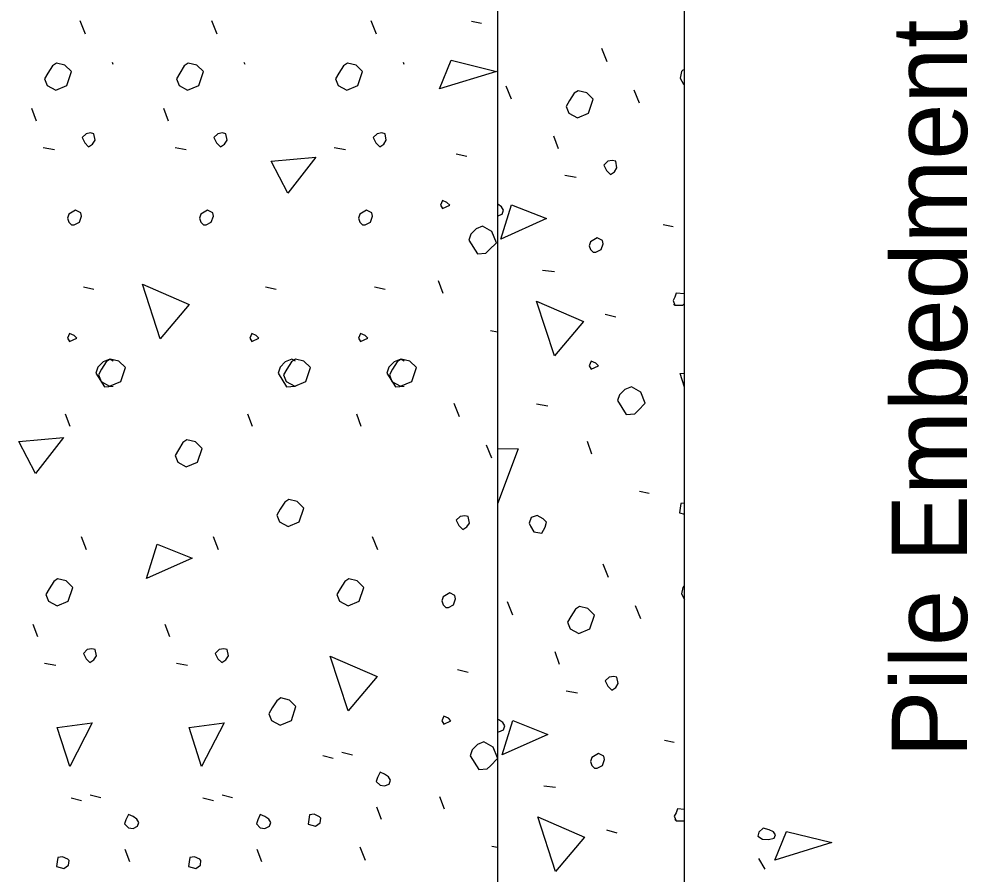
# Model space of a CAD drawing. Extents: x 112310.1 to 112345.4, y 111943.5 to 111959.3.
# Drawn here: x 112320.249 to 112321.522, y 111950.107 to 111951.253 of the extents above; entities that cross this region are included whole.
import ezdxf

# ---------------------------------------------------------------- set-up
doc = ezdxf.new("R2010")
doc.units = 0
for name, color, linetype in [('Miscellaneous', 7, 'Continuous'), ('PileConc', 7, 'Continuous'), ('TextStructures', 7, 'Continuous')]:
    doc.layers.add(name, color=color, linetype=linetype)

msp = doc.modelspace()

# ---------------------------------------------------------------- linework, layer by layer
at = {"layer": 'Miscellaneous'}
for p, q in [((112320.338, 111951.233), (112320.3309, 111951.2506)), ((112320.5149, 111951.233), (112320.5078, 111951.2506)), ((112320.7283, 111951.233), (112320.7212, 111951.2506)), ((112320.8559, 111951.2503), (112320.8691, 111951.2477)), ((112321.0376, 111951.196), (112321.0305, 111951.2137)), ((112320.3753, 111951.1922), (112320.3742, 111951.195)), ((112320.5522, 111951.1922), (112320.5511, 111951.195)), ((112320.7656, 111951.1922), (112320.7645, 111951.195)), ((112320.9094, 111951.1456), (112320.9023, 111951.1633)), ((112321.0809, 111951.1403), (112321.0738, 111951.158)), ((112320.2726, 111951.1163), (112320.2664, 111951.1331)), ((112320.4495, 111951.1163), (112320.4433, 111951.1331)), ((112320.9722, 111951.0793), (112320.966, 111951.0961)), ((112320.2814, 111951.0809), (112320.2964, 111951.0783)), ((112320.4583, 111951.0809), (112320.4733, 111951.0783)), ((112320.6717, 111951.0809), (112320.6867, 111951.0783)), ((112320.8353, 111951.0727), (112320.8494, 111951.0692)), ((112320.981, 111951.044), (112320.996, 111951.0413)), ((112321.1127, 111950.9777), (112321.126, 111950.975)), ((112320.951, 111950.9167), (112320.9669, 111950.9149)), ((112320.3353, 111950.8944), (112320.3495, 111950.8909)), ((112320.5796, 111950.8944), (112320.5937, 111950.8909)), ((112320.7256, 111950.8944), (112320.7398, 111950.8909)), ((112320.8176, 111950.8853), (112320.8114, 111950.9021)), ((112321.0349, 111950.8575), (112321.0491, 111950.8539)), ((112320.8813, 111950.8358), (112320.8907, 111950.834)), ((112320.8397, 111950.72), (112320.8327, 111950.7377)), ((112320.943, 111950.7373), (112320.958, 111950.7346)), ((112320.3176, 111950.707), (112320.3115, 111950.7238)), ((112320.5619, 111950.707), (112320.5557, 111950.7238)), ((112320.708, 111950.707), (112320.7018, 111950.7238)), ((112320.883, 111950.6644), (112320.876, 111950.682)), ((112321.0172, 111950.6701), (112321.0111, 111950.6869)), ((112321.0809, 111950.6206), (112321.0941, 111950.6179)), ((112320.3397, 111950.5418), (112320.3327, 111950.5594)), ((112320.5166, 111950.5418), (112320.5096, 111950.5594)), ((112320.73, 111950.5418), (112320.723, 111950.5594)), ((112321.0393, 111950.5048), (112321.0323, 111950.5225)), ((112320.9112, 111950.4544), (112320.9041, 111950.4721)), ((112321.0827, 111950.4491), (112321.0756, 111950.4668)), ((112320.2743, 111950.4251), (112320.2681, 111950.4419)), ((112320.4512, 111950.4251), (112320.445, 111950.4419)), ((112320.9739, 111950.3881), (112320.9678, 111950.4049)), ((112320.2832, 111950.3897), (112320.2982, 111950.3871)), ((112320.4601, 111950.3897), (112320.4751, 111950.3871)), ((112320.8371, 111950.3815), (112320.8512, 111950.378)), ((112320.9828, 111950.3528), (112320.9978, 111950.3501)), ((112321.1145, 111950.2865), (112321.1277, 111950.2838)), ((112320.6562, 111950.266), (112320.6704, 111950.2624)), ((112320.6819, 111950.2704), (112320.696, 111950.2668)), ((112320.9527, 111950.2255), (112320.9686, 111950.2237)), ((112320.3188, 111950.2092), (112320.333, 111950.2056)), ((112320.3444, 111950.2136), (112320.3586, 111950.21)), ((112320.4957, 111950.2092), (112320.5098, 111950.2056)), ((112320.5213, 111950.2136), (112320.5355, 111950.21)), ((112320.8194, 111950.1941), (112320.8132, 111950.2109)), ((112320.7349, 111950.1802), (112320.7287, 111950.197)), ((112321.0367, 111950.1663), (112321.0508, 111950.1627)), ((112320.883, 111950.1446), (112320.8907, 111950.1431)), ((112320.3975, 111950.1234), (112320.3913, 111950.1402)), ((112320.5744, 111950.1234), (112320.5682, 111950.1402)), ((112320.7137, 111950.1254), (112320.7066, 111950.1431)), ((112321.2495, 111950.1136), (112321.2412, 111950.1281))]:
    msp.add_line(p, q, dxfattribs=at)
for points in [[(112320.2867, 111951.164), (112320.2982, 111951.1578), (112320.3132, 111951.164), (112320.3194, 111951.1826), (112320.3106, 111951.1914), (112320.2991, 111951.1941), (112320.2938, 111951.1905), (112320.2876, 111951.1808), (112320.2832, 111951.1729), (112320.2867, 111951.164)], [(112320.4636, 111951.164), (112320.4751, 111951.1578), (112320.4901, 111951.164), (112320.4963, 111951.1826), (112320.4875, 111951.1914), (112320.476, 111951.1941), (112320.4707, 111951.1905), (112320.4645, 111951.1808), (112320.4601, 111951.1729), (112320.4636, 111951.164)], [(112320.677, 111951.164), (112320.6885, 111951.1578), (112320.7035, 111951.164), (112320.7097, 111951.1826), (112320.7009, 111951.1914), (112320.6894, 111951.1941), (112320.6841, 111951.1905), (112320.6779, 111951.1808), (112320.6735, 111951.1729), (112320.677, 111951.164)], [(112320.8129, 111951.1594), (112320.8286, 111951.1978), (112320.8895, 111951.183), (112320.8129, 111951.1594)], [(112321.1415, 111951.1853), (112321.1392, 111951.1845), (112321.1375, 111951.1827), (112321.1357, 111951.1739)], [(112321.1357, 111951.1739), (112321.1401, 111951.1659), (112321.1415, 111951.1661)], [(112320.9863, 111951.127), (112320.9978, 111951.1209), (112321.0128, 111951.127), (112321.019, 111951.1456), (112321.0102, 111951.1544), (112320.9987, 111951.1571), (112320.9934, 111951.1536), (112320.9872, 111951.1438), (112320.9828, 111951.1359), (112320.9863, 111951.127)], [(112320.3371, 111951.0871), (112320.3424, 111951.0818), (112320.3477, 111951.0853), (112320.3512, 111951.0907), (112320.3495, 111951.0995), (112320.345, 111951.1004), (112320.3389, 111951.0995), (112320.3336, 111951.0942), (112320.3371, 111951.0871)], [(112320.514, 111951.0871), (112320.5193, 111951.0818), (112320.5246, 111951.0853), (112320.5281, 111951.0907), (112320.5263, 111951.0995), (112320.5219, 111951.1004), (112320.5157, 111951.0995), (112320.5104, 111951.0942), (112320.514, 111951.0871)], [(112320.7274, 111951.0871), (112320.7327, 111951.0818), (112320.738, 111951.0853), (112320.7415, 111951.0907), (112320.7398, 111951.0995), (112320.7354, 111951.1004), (112320.7292, 111951.0995), (112320.7239, 111951.0942), (112320.7274, 111951.0871)], [(112320.6094, 111951.0199), (112320.5872, 111951.0628), (112320.6471, 111951.068), (112320.6094, 111951.0199)], [(112321.0367, 111951.0501), (112321.042, 111951.0448), (112321.0473, 111951.0484), (112321.0508, 111951.0537), (112321.0491, 111951.0625), (112321.0446, 111951.0634), (112321.0385, 111951.0625), (112321.0332, 111951.0572), (112321.0367, 111951.0501)], [(112320.8167, 111950.9994), (112320.8265, 111951.0038), (112320.8229, 111951.0073), (112320.8167, 111951.01), (112320.8141, 111951.0038), (112320.8167, 111950.9994)], [(112320.3194, 111950.9775), (112320.3229, 111950.9775), (112320.33, 111950.9811), (112320.3327, 111950.989), (112320.3318, 111950.9934), (112320.3247, 111950.997), (112320.3159, 111950.9917), (112320.3141, 111950.9864), (112320.3159, 111950.9811), (112320.3194, 111950.9775)], [(112320.4963, 111950.9775), (112320.4998, 111950.9775), (112320.5069, 111950.9811), (112320.5096, 111950.989), (112320.5087, 111950.9934), (112320.5016, 111950.997), (112320.4928, 111950.9917), (112320.491, 111950.9864), (112320.4928, 111950.9811), (112320.4963, 111950.9775)], [(112320.7097, 111950.9775), (112320.7133, 111950.9775), (112320.7203, 111950.9811), (112320.723, 111950.989), (112320.7221, 111950.9934), (112320.715, 111950.997), (112320.7062, 111950.9917), (112320.7044, 111950.9864), (112320.7062, 111950.9811), (112320.7097, 111950.9775)], [(112320.8907, 111950.9892), (112320.8909, 111950.9892), (112320.897, 111950.9918), (112320.8988, 111950.9971), (112320.8962, 111951.0015), (112320.8909, 111951.0051), (112320.8907, 111951.0051)], [(112320.8953, 111950.9582), (112320.9094, 111951.0042), (112320.9563, 111950.9856), (112320.8953, 111950.9582)], [(112320.8521, 111950.9569), (112320.8636, 111950.9384), (112320.8751, 111950.9393), (112320.8795, 111950.9437), (112320.8892, 111950.9534), (112320.883, 111950.9684), (112320.8707, 111950.9755), (112320.8618, 111950.972), (112320.8548, 111950.9649), (112320.8521, 111950.9569)], [(112321.019, 111950.9405), (112321.0226, 111950.9405), (112321.0296, 111950.9441), (112321.0323, 111950.952), (112321.0314, 111950.9565), (112321.0243, 111950.96), (112321.0155, 111950.9547), (112321.0137, 111950.9494), (112321.0155, 111950.9441), (112321.019, 111950.9405)], [(112320.4384, 111950.8244), (112320.4145, 111950.8978), (112320.4773, 111950.8704), (112320.4384, 111950.8244)], [(112321.1415, 111950.8849), (112321.1304, 111950.8857), (112321.1286, 111950.8804), (112321.126, 111950.876), (112321.1286, 111950.8698), (112321.1269, 111950.8716)], [(112320.9669, 111950.8018), (112320.943, 111950.8751), (112321.0058, 111950.8477), (112320.9669, 111950.8018)], [(112321.1286, 111950.8698), (112321.1392, 111950.8698), (112321.1415, 111950.8721)], [(112320.3168, 111950.8211), (112320.3265, 111950.8255), (112320.3229, 111950.829), (112320.3168, 111950.8317), (112320.3141, 111950.8255), (112320.3168, 111950.8211)], [(112320.561, 111950.8211), (112320.5708, 111950.8255), (112320.5672, 111950.829), (112320.561, 111950.8317), (112320.5584, 111950.8255), (112320.561, 111950.8211)], [(112320.7071, 111950.8211), (112320.7168, 111950.8255), (112320.7133, 111950.829), (112320.7071, 111950.8317), (112320.7044, 111950.8255), (112320.7071, 111950.8211)], [(112320.3753, 111950.7945), (112320.3707, 111950.7972), (112320.3618, 111950.7937), (112320.3548, 111950.7866), (112320.3521, 111950.7786)], [(112320.359, 111950.7673), (112320.3705, 111950.7612), (112320.3855, 111950.7673), (112320.3917, 111950.7859), (112320.3828, 111950.7947), (112320.3713, 111950.7974), (112320.366, 111950.7939), (112320.3598, 111950.7841), (112320.3554, 111950.7762), (112320.359, 111950.7673)], [(112320.6196, 111950.7945), (112320.6149, 111950.7972), (112320.6061, 111950.7937), (112320.599, 111950.7866), (112320.5964, 111950.7786)], [(112320.6072, 111950.7673), (112320.6187, 111950.7612), (112320.6337, 111950.7673), (112320.6399, 111950.7859), (112320.6311, 111950.7947), (112320.6196, 111950.7974), (112320.6143, 111950.7939), (112320.6081, 111950.7841), (112320.6037, 111950.7762), (112320.6072, 111950.7673)], [(112320.7656, 111950.7945), (112320.761, 111950.7972), (112320.7521, 111950.7937), (112320.7451, 111950.7866), (112320.7424, 111950.7786)], [(112320.7491, 111950.7673), (112320.7606, 111950.7612), (112320.7756, 111950.7673), (112320.7818, 111950.7859), (112320.773, 111950.7947), (112320.7615, 111950.7974), (112320.7562, 111950.7939), (112320.75, 111950.7841), (112320.7456, 111950.7762), (112320.7491, 111950.7673)], [(112321.0164, 111950.7841), (112321.0261, 111950.7885), (112321.0226, 111950.7921), (112321.0164, 111950.7947), (112321.0137, 111950.7885), (112321.0164, 111950.7841)], [(112320.3521, 111950.7786), (112320.3636, 111950.7601), (112320.3751, 111950.761), (112320.3753, 111950.7612)], [(112320.5964, 111950.7786), (112320.6079, 111950.7601), (112320.6194, 111950.761), (112320.6196, 111950.7612)], [(112320.7424, 111950.7786), (112320.7539, 111950.7601), (112320.7654, 111950.761), (112320.7656, 111950.7612)], [(112321.1415, 111950.7598), (112321.1357, 111950.7779), (112321.1415, 111950.7787)], [(112321.0517, 111950.7417), (112321.0632, 111950.7231), (112321.0747, 111950.724), (112321.0791, 111950.7284), (112321.0888, 111950.7381), (112321.0827, 111950.7532), (112321.0703, 111950.7602), (112321.0614, 111950.7567), (112321.0544, 111950.7496), (112321.0517, 111950.7417)], [(112320.2711, 111950.6442), (112320.249, 111950.6871), (112320.3088, 111950.6923), (112320.2711, 111950.6442)], [(112320.4618, 111950.6591), (112320.4733, 111950.6529), (112320.4883, 111950.6591), (112320.4945, 111950.6777), (112320.4857, 111950.6865), (112320.4742, 111950.6892), (112320.4689, 111950.6856), (112320.4627, 111950.6759), (112320.4583, 111950.668), (112320.4618, 111950.6591)], [(112320.8907, 111950.6774), (112320.9183, 111950.6771), (112320.8907, 111950.6034)], [(112320.5984, 111950.5793), (112320.6098, 111950.5731), (112320.6249, 111950.5793), (112320.6311, 111950.5978), (112320.6222, 111950.6067), (112320.6107, 111950.6093), (112320.6054, 111950.6058), (112320.5992, 111950.5961), (112320.5948, 111950.5881), (112320.5984, 111950.5793)], [(112321.1415, 111950.6045), (112321.1366, 111950.6038), (112321.1357, 111950.5976), (112321.1348, 111950.5914)], [(112321.1348, 111950.5914), (112321.1415, 111950.5896)], [(112320.8388, 111950.5742), (112320.8441, 111950.5689), (112320.8494, 111950.5724), (112320.853, 111950.5777), (112320.8512, 111950.5866), (112320.8468, 111950.5875), (112320.8406, 111950.5866), (112320.8353, 111950.5813), (112320.8388, 111950.5742)], [(112320.935, 111950.5737), (112320.9395, 111950.5658), (112320.9501, 111950.564), (112320.9545, 111950.572), (112320.9563, 111950.579), (112320.9518, 111950.5835), (112320.9439, 111950.5879), (112320.9359, 111950.5852), (112320.9333, 111950.5773), (112320.935, 111950.5737)], [(112320.4201, 111950.5034), (112320.4342, 111950.5494), (112320.4811, 111950.5308), (112320.4201, 111950.5034)], [(112320.2885, 111950.4728), (112320.3, 111950.4666), (112320.315, 111950.4728), (112320.3212, 111950.4914), (112320.3123, 111950.5002), (112320.3008, 111950.5029), (112320.2955, 111950.4993), (112320.2894, 111950.4896), (112320.2849, 111950.4817), (112320.2885, 111950.4728)], [(112320.6788, 111950.4728), (112320.6903, 111950.4666), (112320.7053, 111950.4728), (112320.7115, 111950.4914), (112320.7026, 111950.5002), (112320.6912, 111950.5029), (112320.6859, 111950.4993), (112320.6797, 111950.4896), (112320.6752, 111950.4817), (112320.6788, 111950.4728)], [(112321.1415, 111950.4935), (112321.141, 111950.4933), (112321.1392, 111950.4915), (112321.1375, 111950.4827)], [(112320.8212, 111950.4646), (112320.8247, 111950.4646), (112320.8318, 111950.4681), (112320.8344, 111950.4761), (112320.8335, 111950.4805), (112320.8265, 111950.4841), (112320.8176, 111950.4787), (112320.8159, 111950.4734), (112320.8176, 111950.4681), (112320.8212, 111950.4646)], [(112321.1375, 111950.4827), (112321.1415, 111950.4754)], [(112320.9881, 111950.4358), (112320.9996, 111950.4297), (112321.0146, 111950.4358), (112321.0208, 111950.4544), (112321.0119, 111950.4632), (112321.0005, 111950.4659), (112320.9952, 111950.4624), (112320.989, 111950.4526), (112320.9845, 111950.4447), (112320.9881, 111950.4358)], [(112320.3389, 111950.3959), (112320.3442, 111950.3906), (112320.3495, 111950.3942), (112320.353, 111950.3995), (112320.3512, 111950.4083), (112320.3468, 111950.4092), (112320.3406, 111950.4083), (112320.3353, 111950.403), (112320.3389, 111950.3959)], [(112320.5157, 111950.3959), (112320.521, 111950.3906), (112320.5263, 111950.3942), (112320.5299, 111950.3995), (112320.5281, 111950.4083), (112320.5237, 111950.4092), (112320.5175, 111950.4083), (112320.5122, 111950.403), (112320.5157, 111950.3959)], [(112320.6902, 111950.3258), (112320.6663, 111950.3992), (112320.7291, 111950.3718), (112320.6902, 111950.3258)], [(112321.0385, 111950.359), (112321.0438, 111950.3536), (112321.0491, 111950.3572), (112321.0526, 111950.3625), (112321.0508, 111950.3713), (112321.0464, 111950.3722), (112321.0402, 111950.3713), (112321.0349, 111950.366), (112321.0385, 111950.359)], [(112320.5877, 111950.3131), (112320.5992, 111950.3069), (112320.6142, 111950.3131), (112320.6204, 111950.3317), (112320.6116, 111950.3405), (112320.6001, 111950.3432), (112320.5948, 111950.3396), (112320.5886, 111950.3299), (112320.5842, 111950.322), (112320.5877, 111950.3131)], [(112320.317, 111950.2516), (112320.3002, 111950.3037), (112320.3471, 111950.3099), (112320.317, 111950.2516)], [(112320.4939, 111950.2516), (112320.4771, 111950.3037), (112320.524, 111950.3099), (112320.4939, 111950.2516)], [(112320.8185, 111950.3082), (112320.8282, 111950.3126), (112320.8247, 111950.3161), (112320.8185, 111950.3188), (112320.8159, 111950.3126), (112320.8185, 111950.3082)], [(112320.8907, 111950.2982), (112320.8926, 111950.298), (112320.8988, 111950.3006), (112320.9006, 111950.3059), (112320.8979, 111950.3103), (112320.8926, 111950.3139), (112320.8907, 111950.3147)], [(112320.897, 111950.267), (112320.9112, 111950.313), (112320.958, 111950.2944), (112320.897, 111950.267)], [(112320.8907, 111950.2629), (112320.8848, 111950.2772), (112320.8724, 111950.2843), (112320.8636, 111950.2808), (112320.8565, 111950.2737), (112320.8539, 111950.2657)], [(112320.8539, 111950.2657), (112320.8654, 111950.2472), (112320.8768, 111950.2481), (112320.8813, 111950.2525), (112320.8907, 111950.2619)], [(112321.0208, 111950.2493), (112321.0243, 111950.2493), (112321.0314, 111950.2529), (112321.034, 111950.2608), (112321.0332, 111950.2653), (112321.0261, 111950.2688), (112321.0172, 111950.2635), (112321.0155, 111950.2582), (112321.0172, 111950.2529), (112321.0208, 111950.2493)], [(112320.7331, 111950.2262), (112320.7393, 111950.2253), (112320.7455, 111950.2279), (112320.7473, 111950.2332), (112320.7446, 111950.2377), (112320.7393, 111950.2412), (112320.7331, 111950.2439), (112320.7296, 111950.2368), (112320.7278, 111950.2315), (112320.7331, 111950.2262)], [(112321.1415, 111950.1938), (112321.1322, 111950.1945), (112321.1304, 111950.1892), (112321.1277, 111950.1848), (112321.1304, 111950.1786), (112321.1286, 111950.1804)], [(112320.3957, 111950.1694), (112320.4019, 111950.1685), (112320.4081, 111950.1712), (112320.4098, 111950.1765), (112320.4072, 111950.1809), (112320.4019, 111950.1844), (112320.3957, 111950.1871), (112320.3922, 111950.18), (112320.3904, 111950.1747), (112320.3957, 111950.1694)], [(112320.5726, 111950.1694), (112320.5788, 111950.1685), (112320.585, 111950.1712), (112320.5867, 111950.1765), (112320.5841, 111950.1809), (112320.5788, 111950.1844), (112320.5726, 111950.1871), (112320.5691, 111950.18), (112320.5673, 111950.1747), (112320.5726, 111950.1694)], [(112320.6368, 111950.174), (112320.6465, 111950.1714), (112320.6527, 111950.1758), (112320.6536, 111950.182), (112320.6518, 111950.1838), (112320.6448, 111950.1873), (112320.6386, 111950.1864), (112320.6377, 111950.1802), (112320.6368, 111950.174)], [(112320.9686, 111950.1106), (112320.9448, 111950.1839), (112321.0075, 111950.1565), (112320.9686, 111950.1106)], [(112321.1304, 111950.1786), (112321.141, 111950.1786), (112321.1415, 111950.1792)], [(112321.2459, 111950.154), (112321.2538, 111950.1534), (112321.2614, 111950.1555), (112321.2632, 111950.1597), (112321.2609, 111950.164), (112321.2548, 111950.1667), (112321.2469, 111950.1689), (112321.241, 111950.1633), (112321.2398, 111950.1581), (112321.2459, 111950.154)], [(112321.2624, 111950.126), (112321.2782, 111950.1644), (112321.3391, 111950.1496), (112321.2624, 111950.126)], [(112320.2994, 111950.1172), (112320.3091, 111950.1146), (112320.3153, 111950.119), (112320.3162, 111950.1252), (112320.3144, 111950.127), (112320.3073, 111950.1305), (112320.3011, 111950.1296), (112320.3002, 111950.1234), (112320.2994, 111950.1172)], [(112320.4762, 111950.1172), (112320.486, 111950.1146), (112320.4922, 111950.119), (112320.493, 111950.1252), (112320.4913, 111950.127), (112320.4842, 111950.1305), (112320.478, 111950.1296), (112320.4771, 111950.1234), (112320.4762, 111950.1172)]]:
    msp.add_lwpolyline(points, dxfattribs=at)
at = {"layer": 'PileConc'}
for p, q in [((112320.8907, 111951.8505), (112320.8907, 111949.007)), ((112321.1415, 111949.007), (112321.1415, 111951.8151))]:
    msp.add_line(p, q, dxfattribs=at)

# ---------------------------------------------------------------- texts
at = {"layer": 'TextStructures'}
msp.add_text('Pile Embedment', height=0.1008, rotation=90, dxfattribs=at).set_placement((112321.5201, 111950.2632))

doc.saveas('drawing.dxf')
